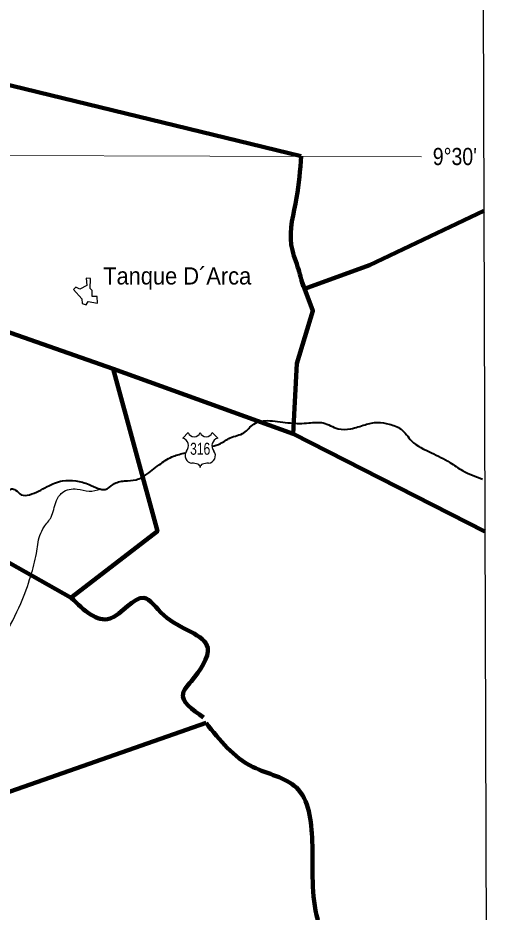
# Model space of a CAD drawing. Extents: x 553962 to 842807, y 8883888 to 9032388.
# Drawn here: x 779754 to 793496, y 8927062 to 8953102 of the extents above; entities that cross this region are included whole.
import ezdxf
from ezdxf.enums import TextEntityAlignment as Align

# ---------------------------------------------------------------- set-up
doc = ezdxf.new("R2010")
doc.units = 0
doc.header["$LTSCALE"] = 20
for name, color, linetype, lineweight in [('1', 7, 'Continuous', 13), ('12', 7, 'Continuous', 25), ('21', 7, 'Continuous', 25), ('3', 7, 'Continuous', 13), ('48', 7, 'Continuous', 25), ('9', 7, 'Continuous', 90)]:
    doc.layers.add(name, color=color, linetype=linetype, lineweight=lineweight)
doc.layers.add('41', color=7, linetype='Continuous')
doc.layers.add('46', color=7, linetype='Continuous')

msp = doc.modelspace()

# ---------------------------------------------------------------- linework, layer by layer
at = {"layer": '1'}
msp.add_line((565315.27, 8949866.81), (791497.68, 8949052.23), dxfattribs=at)
at = {"layer": '12', "lineweight": 40}
for points in [[(761549.23, 8957020.39), (762383.1, 8955993.89), (763257, 8954902.9), (764214.4, 8953717.28), (766168.17, 8951324.42), (767086.6, 8950171.63), (770317.83, 8946184.23), (771971.01, 8944145.98), (773006.34, 8942876.25), (773223.42, 8942642.35), (773373.71, 8942274.8), (774008.27, 8940921.53), (774358.95, 8940136.3), (774475.84, 8939919.11), (774642.83, 8939785.46), (774893.31, 8939668.51), (775511.17, 8939484.73), (775928.64, 8939267.54), (776078.93, 8939184), (776379.51, 8938916.69), (776680.09, 8938749.62), (776830.38, 8938582.55), (777398.14, 8938348.65), (777899.1, 8938231.71), (778550.36, 8938482.31), (779134.82, 8938866.57), (779452.1, 8939250.83), (779568.99, 8939384.49), (779685.88, 8939351.07), (779852.87, 8939217.42), (780086.65, 8939217.42), (780604.32, 8939451.32), (781055.19, 8939618.39), (781439.26, 8939618.39), (781823.33, 8939518.14), (782090.52, 8939401.2), (782290.9, 8939367.78), (782524.69, 8939518.14), (782858.66, 8939618.39), (783192.64, 8939651.8), (783509.92, 8939818.87), (783910.69, 8940119.6), (784278.07, 8940336.79), (784625.22, 8940434.47)], [(785398.34, 8940626.9), (785647.37, 8940704.34), (785931.25, 8940871.41), (786332.02, 8941021.78), (786615.9, 8941272.38), (787083.47, 8941372.62), (787684.63, 8941305.79), (788218.99, 8941305.79), (788636.47, 8941305.79), (789070.64, 8941138.72), (789438.01, 8941138.72), (789855.48, 8941255.67)], [(789855.48, 8941255.67), (790222.86, 8941322.5), (790556.83, 8941272.38), (790907.51, 8941122.02), (791208.09, 8940787.88), (791792.55, 8940437.03), (792326.91, 8940153.01), (792694.29, 8939919.11), (793278.75, 8939668.51)]]:
    msp.add_spline(points, degree=3, dxfattribs=at)
at = {"layer": '12'}
msp.add_spline([(774356.66, 8932040.89), (774893.9, 8932329.29), (775282.36, 8932656.41), (775507.25, 8932942.65), (775793.48, 8933065.31), (776774.84, 8933249.32), (777572.2, 8933412.88), (777960.65, 8933535.55), (778451.33, 8933985.34), (778901.12, 8934353.35), (779350.91, 8935068.93), (779841.59, 8936050.29), (780127.82, 8936847.64), (780291.38, 8937501.88), (780393.61, 8938033.45), (780516.28, 8938278.79), (780720.73, 8938565.02), (780863.84, 8939014.81), (781047.85, 8939280.59), (781477.19, 8939382.82), (781824.76, 8939321.49), (782163.73, 8939377.82)], degree=3, dxfattribs=at)
at = {"layer": '21'}
msp.add_lwpolyline([(782067.98, 8944791.62), (782057.65, 8944984.81), (781912.32, 8944989.14), (781919.27, 8945159.54), (781854.82, 8945223.03), (781862.97, 8945498.72), (781863.17, 8945516.27), (781742.95, 8945525.31), (781760.53, 8945306.96), (781556.3, 8945201.72), (781439.1, 8945255.85), (781368.16, 8945189.05), (781618.27, 8944920.14), (781624.3, 8944789.68), (781739.13, 8944748.12), (781797.83, 8944840.15)], close=True, dxfattribs=at)
at = {"layer": '3', "lineweight": 25}
msp.add_lwpolyline([(563033.89, 9026438.81), (793061.13, 9026438.81), (793495.55, 8889836.82), (563468.3, 8889836.82)], close=True, dxfattribs=at)
at = {"layer": '48'}
for p, q in [((784549.35, 8940864.53), (784709.28, 8941024.43)), ((785408.6, 8941024.43), (785568.55, 8940864.53))]:
    msp.add_line(p, q, dxfattribs=at)
for centre, radius, start, end in [((784884.12, 8941091.4), 187.21, 200.95927, 339.04073), ((785233.77, 8941091.4), 187.21, 200.95927, 339.04073), ((784487.28, 8940642.66), 230.34, 317.5721, 74.36886), ((785630.6, 8940642.66), 230.34, 105.62774, 222.4279), ((784840.78, 8940357.52), 224.71, 144.73733, 264.65778), ((785277.1, 8940357.52), 224.71, 275.34222, 35.26267), ((784818.83, 8939544.05), 589.74, 72.89371, 89.90057), ((784964.58, 8940017.42), 94.44, 357.69345, 72.92955), ((785153.3, 8940017.42), 94.44, 107.07045, 182.30655), ((785299.05, 8939544.05), 589.74, 90.09943, 107.10629)]:
    msp.add_arc(centre, radius, start, end, dxfattribs=at)
at = {"layer": '9'}
for p, q in [((779222.16, 8951211.15), (787994.96, 8949076.72)), ((782526.08, 8942878.47), (771355.16, 8946811.13)), ((787760.76, 8940985.82), (793341.93, 8938140.96)), ((787760.76, 8940985.82), (793341.93, 8938140.96))]:
    msp.add_line(p, q, dxfattribs=at)
for points in [[(793312.23, 8947480.42), (789981.24, 8945898.96), (788096.89, 8945214.43)], [(793312.23, 8947480.42), (789981.24, 8945898.96), (788096.89, 8945214.43)], [(782526.08, 8942878.47), (787760.76, 8940985.82), (787869.59, 8943035.4), (788337.5, 8944573.77), (788005.22, 8945458.5)], [(769262.28, 8944467.07), (774822.07, 8939873.46), (781306.63, 8936216.87)], [(781336.56, 8936240.01), (783812.04, 8938154.37), (782526.08, 8942878.47)], [(785227.98, 8932570.74), (773847.73, 8928582.93), (772905.66, 8929437.75), (766683.65, 8930666.83), (762959.33, 8929647.41)]]:
    msp.add_lwpolyline(points, dxfattribs=at)
for points in [[(788054.47, 8945281.65), (787894.37, 8945856.54), (787708.91, 8946496.16), (787865.56, 8947860), (787994.96, 8949076.72)], [(785158.05, 8932730.45), (784558.65, 8933435.97), (784793.4, 8933780.09), (785277.18, 8934758.07), (784000.54, 8935708.84), (783413.96, 8936210.55), (782437.61, 8935613.13), (781306.63, 8936216.87)], [(785227.98, 8932570.74), (786596.92, 8931287.53), (787857.17, 8930689.45), (788319.95, 8929128.33), (788478.31, 8926833.75), (789430.8, 8925249.35), (791075.73, 8923916.12), (791912.02, 8922868.02)]]:
    msp.add_spline(points, degree=3, dxfattribs=at)

# ---------------------------------------------------------------- texts
at = {"layer": '41', "width": 0.95}
msp.add_text('Tanque D´Arca', height=500, dxfattribs=at).set_placement((782236.34, 8945338.2))
at = {"layer": '46', "width": 0.85}
msp.add_text("9°30'", height=500, dxfattribs=at).set_placement((792469.34, 8948815.92), align=Align.CENTER)
at = {"layer": '48', "width": 0.75}
msp.add_text('316', height=350, dxfattribs=at).set_placement((785058.52, 8940380.2), align=Align.CENTER)

doc.saveas('drawing.dxf')
